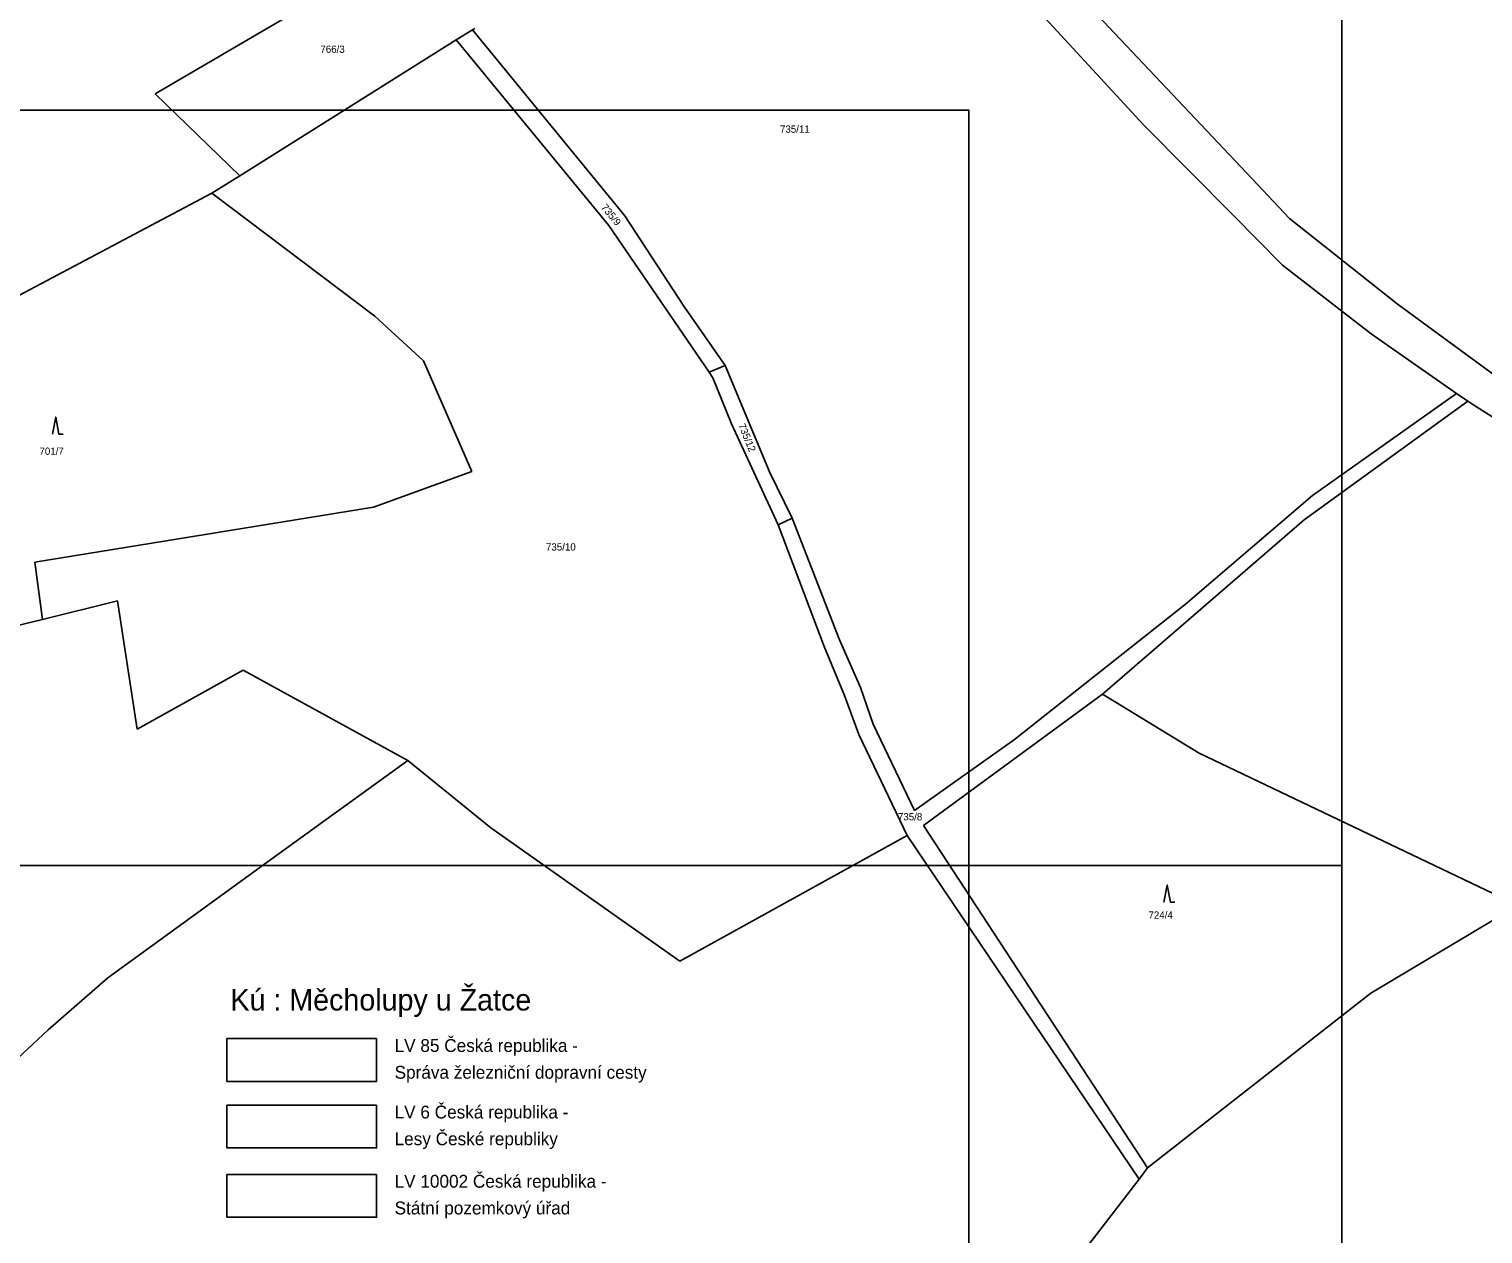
# Model space of a CAD drawing. Extents: x -801907 to -800293, y -1017000 to -1015684.
# Drawn here: x -800931.6 to -800592.1, y -1016586 to -1016304.7 of the extents above; entities that cross this region are included whole.
import ezdxf

# ---------------------------------------------------------------- set-up
doc = ezdxf.new("R2010")
doc.units = 0
for name, color, linetype in [('Default', 7, 'Continuous'), ('KLADY_ZMVM', 7, 'Continuous'), ('KN_HRANICE', 7, 'Continuous'), ('KN_KULTURY', 7, 'Continuous'), ('KN_PARCELY', 7, 'Continuous'), ('LEGENDA', 7, 'Continuous')]:
    doc.layers.add(name, color=color, linetype=linetype)

# ---------------------------------------------------------------- blocks, each defined once
blk = doc.blocks.new('308')
at = {"layer": 'Default'}
blk.add_lwpolyline([(-0.75, 0), (0, 4), (0.75, 0), (1.75, 0)], dxfattribs=at)

msp = doc.modelspace()

# ---------------------------------------------------------------- linework, layer by layer
at = {"layer": 'KLADY_ZMVM'}
msp.add_line((-801250, -1016500), (-800625, -1016500), dxfattribs=at)
msp.add_lwpolyline([(-800625, -1016000), (-800625, -1016500), (-800625, -1017000)], dxfattribs=at)
at = {"layer": 'KN_HRANICE'}
for p, q in [((-800902.15, -1016319.78), (-800832.94, -1016279.31)), ((-800693.94, -1016288.84), (-800661.88, -1016322.76)), ((-800701.43, -1016294.3), (-800671.28, -1016327.06)), ((-800828.01, -1016304.81), (-800831.82, -1016307.2)), ((-800827.51, -1016304.5), (-800828.01, -1016304.81)), ((-800828.01, -1016304.81), (-800792.42, -1016348.23)), ((-800831.82, -1016307.2), (-800882.39, -1016338.89)), ((-800796.15, -1016350.5), (-800831.82, -1016307.2)), ((-800882.39, -1016338.89), (-800902.15, -1016319.78)), ((-800661.88, -1016322.76), (-800645.93, -1016339.64)), ((-800671.28, -1016327.06), (-800650.33, -1016348.18)), ((-800882.39, -1016338.89), (-800888.88, -1016342.96)), ((-800645.93, -1016339.64), (-800637.22, -1016348.86)), ((-800888.88, -1016342.96), (-800989.55, -1016396.29)), ((-800888.88, -1016342.96), (-800850.85, -1016371.7)), ((-800792.42, -1016348.23), (-800778.66, -1016369.34)), ((-800650.33, -1016348.18), (-800638.85, -1016359.75)), ((-800637.22, -1016348.86), (-800612.1, -1016368.85)), ((-800772.77, -1016384.8), (-800796.15, -1016350.5)), ((-800638.85, -1016359.75), (-800618.15, -1016375.86)), ((-800778.66, -1016369.34), (-800769.02, -1016383.23)), ((-800612.1, -1016368.85), (-800587.87, -1016386.56)), ((-800850.85, -1016371.7), (-800839.44, -1016382.12)), ((-800618.15, -1016375.86), (-800598.22, -1016389.73)), ((-800839.44, -1016382.12), (-800828.17, -1016407.96)), ((-800772.77, -1016384.8), (-800769.02, -1016383.23)), ((-800769.02, -1016383.23), (-800758.65, -1016408.03)), ((-800771.89, -1016386.09), (-800772.77, -1016384.8)), ((-800767.55, -1016396.86), (-800771.89, -1016386.09)), ((-800631.89, -1016413.56), (-800598.22, -1016389.73)), ((-800598.22, -1016389.73), (-800595.57, -1016391.58)), ((-800633.84, -1016419.29), (-800595.57, -1016391.58)), ((-800595.57, -1016391.58), (-800594.45, -1016392.36)), ((-800594.45, -1016392.36), (-800517.53, -1016440.89)), ((-800756.61, -1016420.44), (-800767.55, -1016396.86)), ((-800828.17, -1016407.96), (-800851.17, -1016416.29)), ((-800758.65, -1016408.03), (-800753.36, -1016418.9)), ((-800661.55, -1016438.97), (-800631.89, -1016413.56)), ((-800851.17, -1016416.29), (-800930.26, -1016429.17)), ((-800753.36, -1016418.9), (-800756.61, -1016420.44)), ((-800745.94, -1016448.84), (-800756.61, -1016420.44)), ((-800753.36, -1016418.9), (-800742.32, -1016447.29)), ((-800680.93, -1016459.96), (-800633.84, -1016419.29)), ((-800930.26, -1016429.17), (-800928.47, -1016442.57)), ((-800928.47, -1016442.57), (-800910.92, -1016438.2)), ((-800910.92, -1016438.2), (-800906.36, -1016468.13)), ((-800701.47, -1016470.52), (-800661.55, -1016438.97)), ((-800987.67, -1016456.78), (-800928.47, -1016442.57)), ((-800742.32, -1016447.29), (-800737.41, -1016458.44)), ((-800741.13, -1016460.27), (-800745.94, -1016448.84)), ((-800906.36, -1016468.13), (-800881.56, -1016454.34)), ((-800881.56, -1016454.34), (-800843.12, -1016475.44)), ((-800737.82, -1016469.42), (-800741.13, -1016460.27)), ((-800737.41, -1016458.44), (-800734.48, -1016466.94)), ((-800722.74, -1016490.67), (-800680.93, -1016459.96)), ((-800680.93, -1016459.96), (-800658.32, -1016473.75)), ((-800734.48, -1016466.94), (-800724.77, -1016487.12)), ((-800726.49, -1016492.96), (-800737.82, -1016469.42)), ((-800724.77, -1016487.12), (-800701.47, -1016470.52)), ((-800658.32, -1016473.75), (-800583.94, -1016509.31)), ((-800876, -1016499.2), (-800843.12, -1016475.44)), ((-800843.12, -1016475.44), (-800823.71, -1016491.19)), ((-800823.71, -1016491.19), (-800779.57, -1016522.34)), ((-800670.38, -1016570.61), (-800722.74, -1016490.67)), ((-800779.57, -1016522.34), (-800726.49, -1016492.96)), ((-800726.49, -1016492.96), (-800694.98, -1016539.69)), ((-800913.21, -1016526.21), (-800876, -1016499.2)), ((-800583.94, -1016509.31), (-800618.21, -1016529.77)), ((-800927.12, -1016538.33), (-800913.21, -1016526.21)), ((-800618.21, -1016529.77), (-800670.38, -1016570.61)), ((-800944.95, -1016554.98), (-800927.12, -1016538.33)), ((-800694.98, -1016539.69), (-800672.38, -1016573.21)), ((-800672.38, -1016573.21), (-800702.65, -1016612.58)), ((-800670.38, -1016570.61), (-800672.38, -1016573.21))]:
    msp.add_line(p, q, dxfattribs=at)
at = {"layer": 'LEGENDA'}
for p, q in [((-800885.43, -1016540.41), (-800850.43, -1016540.41)), ((-800885.43, -1016540.41), (-800885.43, -1016550.41)), ((-800885.43, -1016555.95), (-800850.43, -1016555.95)), ((-800885.43, -1016555.95), (-800885.43, -1016565.95)), ((-800885.43, -1016572.11), (-800850.43, -1016572.11)), ((-800885.43, -1016572.11), (-800885.43, -1016582.11))]:
    msp.add_line(p, q, dxfattribs=at)
msp.add_lwpolyline([(-801306.12, -1016323.56), (-800712.12, -1016323.56), (-800712.12, -1016743.56), (-801306.12, -1016743.56)], close=True, dxfattribs=at)
for points in [[(-800850.43, -1016540.41), (-800850.43, -1016550.41), (-800885.43, -1016550.41)], [(-800850.43, -1016555.95), (-800850.43, -1016565.95), (-800885.43, -1016565.95)], [(-800850.43, -1016572.11), (-800850.43, -1016582.11), (-800885.43, -1016582.11)]]:
    msp.add_lwpolyline(points, dxfattribs=at)

# ---------------------------------------------------------------- block references
at = {"layer": 'KN_KULTURY'}
for p in [(-800925.34, -1016399.28), (-800665.8, -1016508.54)]:
    msp.add_blockref('308', p, dxfattribs=at)

# ---------------------------------------------------------------- texts
at = {"layer": 'KN_PARCELY'}
for s, p in [('766/3', (-800863.55, -1016310.21)), ('735/11', (-800756.22, -1016328.87)), ('701/7', (-800929.15, -1016404.07)), ('735/10', (-800810.87, -1016426.43)), ('735/8', (-800728.68, -1016489.45)), ('724/4', (-800670.17, -1016512.41))]:
    msp.add_text(s, height=1.7, dxfattribs=at).set_placement(p)
for s, rotation, p in [('735/9', 309.283, (-800798.1, -1016346.35)), ('735/12', 292.438, (-800766.01, -1016397.16))]:
    msp.add_text(s, height=1.7, rotation=rotation, dxfattribs=at).set_placement(p)
at = {"layer": 'LEGENDA'}
for s, height, p in [('Kú : Měcholupy u Žatce', 5, (-800884.55, -1016533.85)), ('LV 85 Česká republika -', 3, (-800846.22, -1016543.52)), ('Správa železniční dopravní cesty', 3, (-800846.22, -1016549.77)), ('LV 6 Česká republika -', 3, (-800846.22, -1016559.06)), ('Lesy České republiky', 3, (-800846.22, -1016565.3)), ('LV 10002 Česká republika -', 3, (-800846.22, -1016575.22)), ('Státní pozemkový úřad', 3, (-800846.22, -1016581.46))]:
    msp.add_text(s, height=height, dxfattribs=at).set_placement(p)

doc.saveas('drawing.dxf')
